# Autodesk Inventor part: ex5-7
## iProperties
Shininess: 64.0
Length Units: 11272
Angle Units: 11279
Time Units: 11290
Mass Units: 11286
Length Display Precision: 3
Angle Display Precision: 2
Compacted: True
Part Number: ex5-7
Document SubType Name: Modeling
Created: 2003-11
Designer: Elise Moss
Cost Center: 0 lbmass
Authority: 1.03 in^3
Manufacturer: Standard
Standards Organization: Custom
Density: 0.0
Volumn: 0.0
Area: 0.0
PropertySet Name: Model Information
Control State: 0
Master: False
Checked Out: False
SaveDate: 2003-11-15
SaveTime: 20:03
TotalMass: 0 lbmass
TotalVolume: 1.03 in^3
Author: Elise Moss
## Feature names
1. Loft1
